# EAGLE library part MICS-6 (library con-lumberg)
CONNECTOR
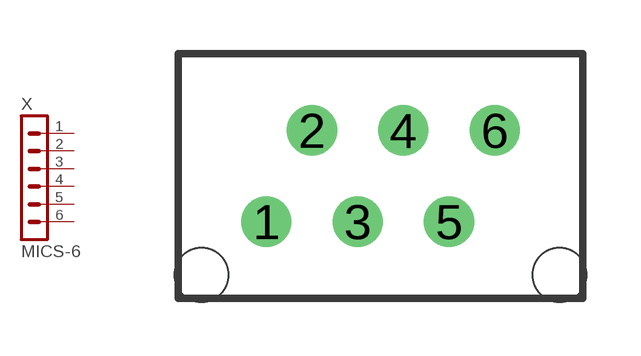
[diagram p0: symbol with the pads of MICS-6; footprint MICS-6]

Designator prefix X

## MICS-6 (OC_FARNELL: unknown; OC_NEWARK: unknown)  [MICS-6]
1  1  pas
2  2  pas
3  3  pas
4  4  pas
5  5  pas
6  6  pas

## Footprint MICS-6 (pad centres in mm)
CONNECTOR
drill 0.85 pad 1.397 round: 1 -3.175,-1.27; 2 -1.905,1.27; 3 -0.635,-1.27; 4 0.635,1.27; 5 1.905,-1.27; 6 3.175,1.27
hole 1.5 at 4.975,-2.75
hole 1.5 at -4.975,-2.75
